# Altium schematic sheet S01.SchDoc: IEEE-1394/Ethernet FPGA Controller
size 381 x 254 mm; Revision: 3.2; SheetNumber: 1; SheetTotal: 10; PageSetup: Record=PageOptions¦CenterHorizontal=True¦CenterVertical=True¦PrintScale=1.08¦XCorrection=1.00¦YCorrection=1.00¦PrintKind=1¦BorderSize=5000000¦LeftOffset=0¦BottomOffset=0¦Orientation=2¦PaperLength=1000¦PaperWidth=1000¦Scale=100¦PaperSource=7¦PrintQuality=600¦MediaType=1¦DitherType=10¦PrintScaleMode=1¦PaperKind=Ledger¦PaperIndex=3
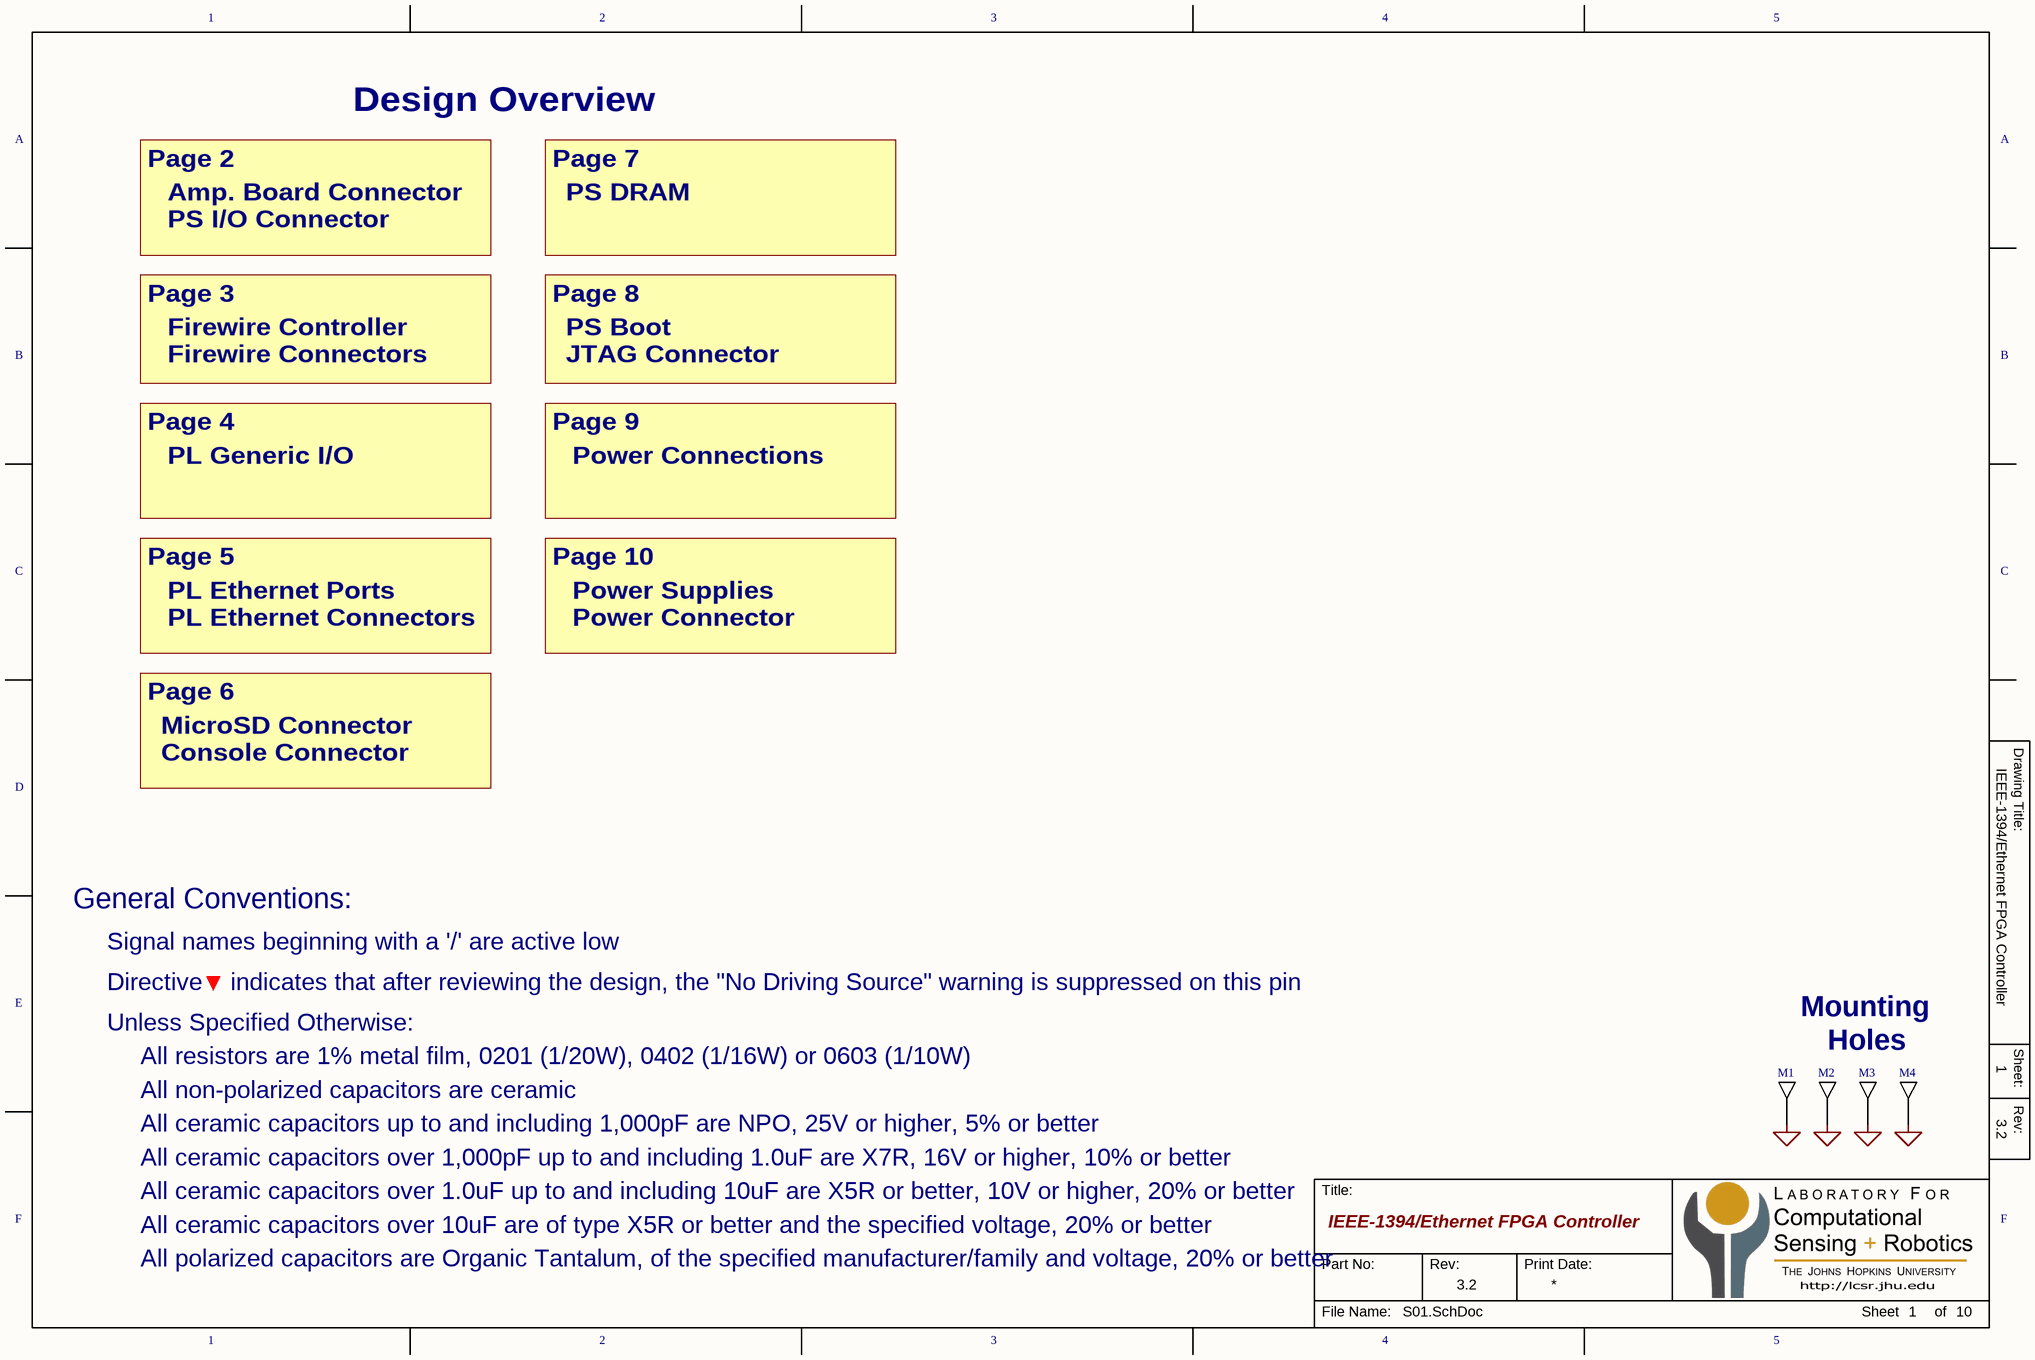
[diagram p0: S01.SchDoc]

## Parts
M1  MHOLE  [MHOLE4]  (value not drawn)  (no BOM)
M2  MHOLE  [MHOLE4]  (value not drawn)  (no BOM)
M3  MHOLE  [MHOLE4]  (value not drawn)  (no BOM)
M4  MHOLE  [MHOLE4]  (value not drawn)  (no BOM)

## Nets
GND: M1.1 M2.1 M3.1 M4.1

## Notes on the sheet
- Page 2
- Design Overview
- Page 7
- Amp. Board Connector
- PS I/O Connector
- PS DRAM
- Page 3
- Page 8
- Firewire Controller
- Firewire Connectors
- PS Boot
- JTAG Connector
- Page 4
- Page 9
- PL Generic I/O
- Power Connections
- Page 5
- Page 10
- PL Ethernet Connectors
- PL Ethernet Ports
- Power Connector
- Power Supplies
- Page 6
- Console Connector
- MicroSD Connector
- General Conventions:
- Signal names beginning with a '/' are active low
- Unless Specified Otherwise:
- Directive    indicates that after reviewing the design, the "No Driving Source" warning is suppressed on this pin
- Mounting
- All resistors are 1% metal film, 0201 (1/20W), 0402 (1/16W) or 0603 (1/10W)
- All non-polarized capacitors are ceramic
- Holes
- All ceramic capacitors up to and including 1,000pF are NPO, 25V or higher, 5% or better
- All ceramic capacitors over 1,000pF up to and including 1.0uF are X7R, 16V or higher, 10% or better
- All ceramic capacitors over 10uF are of type X5R or better and the specified voltage, 20% or better
- All ceramic capacitors over 1.0uF up to and including 10uF are X5R or better, 10V or higher, 20% or better
- All polarized capacitors are Organic Tantalum, of the specified manufacturer/family and voltage, 20% or better

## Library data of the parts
M1-M4 = MHOLE: Mounting Hole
